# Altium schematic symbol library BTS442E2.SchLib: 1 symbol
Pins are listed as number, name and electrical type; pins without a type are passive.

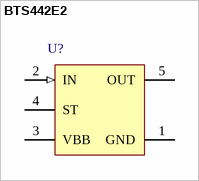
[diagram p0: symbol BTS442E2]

## BTS442E2
designator U?
Smart High-Side Power Switch, 1 Channel, 7.5 A Load Current, -40 to 150 degC, PG-TO220-5-3, Tube, Green; Manufacturer: Infineon; PartNumber: BTS442E2; Channels: 1; Green: TRUE; Group: Automotive Qualified; Load Current (typ): 7.5 A; Recommended Operating Voltage Max.: 42 V; Recommended Operating Voltage Min.: 4.5 V; RON @ 25degreesC: 18 mOhm; RON(max) @ 150degreesC: 35 mOhm
footprint INF-PG-TO220-5-3 (FM, 5-Leads, Body 9.9x4.4mm, Pitch 1.7mm)
pins: 1 GND (power) "Logic ground", 2 IN (in) "Input, activates the power switch in case of logical high signal", 3 VBB (power) "Positive power supply voltage, the tab is shorted to this pin", 4 ST (oc) "Diagnostic feedback, low on failure", 5 OUT (power) "Output to the load"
